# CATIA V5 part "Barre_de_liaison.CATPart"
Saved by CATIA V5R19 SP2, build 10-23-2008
Part number: Barre_de_liaison
Bounding box of the stored display mesh (mm): x -16 to -4, y -304 to 0, z -105.955 to -86.045
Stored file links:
  G:\EU_thinkMotion\CFAO_2010\MMS_groupe3\MMS_groupe3\pmayet\pmayet_assemblage_animation\pmayet_assemblage_animation\Barre_de_liaison.CATPart
  G:\EU_thinkMotion\CFAO_2010\MMS_groupe3\MMS_groupe3\pmayet\pmayet_assemblage_animation\pmayet_assemblage_animation\pmayet_assemblage_animation.CATProduct
  G:\EU_thinkMotion\CFAO_2010\MMS_groupe3\MMS_groupe3\pmayet\pmayet_assemblage_animation\pmayet_assemblage_animation\Squelette_barre_de_liaison.CATPart
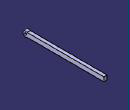
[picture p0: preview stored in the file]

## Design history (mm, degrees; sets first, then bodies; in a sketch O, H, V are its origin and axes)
Parameters
  Rayon_trou_barre_de_liaison = 4 mm
  Epaisseur_barre_de_liaison = 6 mm
Set1
  Plane1: linked copy from another document
  Point1 "Point.22_barre_liaison": linked copy from another document
  Line1: linked copy from another document
  Point2 "Point.23_barre_liaison_2": linked copy from another document
Body1 (main body)
  Sketch1 on Plane1, origin (-10, 0, 0), H (0, 1, 0), V (0, 0, 1)
    arc A1 centre (-294, -96) radius 10 from (-288, -88) to (-288, -104) ccw
    point P1 (-294, -96)
    point P2 (-288, -88)
    point P3 (-288, -104)
    line L1 (-288, -88) -> (0, -88)
    point P4 (-288, -88)
    point P5 (0, -88)
    line L2 (-288, -104) -> (0, -104)
    point P6 (-288, -104)
    point P7 (0, -104)
    line L3 (0, -88) -> (0, -104)
    point P8 (0, -88)
    point P9 (0, -104)
    circle A2 centre (-294, -96) radius 4
    point P10 (-294, -96)
    reference projected point E1 (-294, -96) from Point1
    reference projected point E2 (-294, -96) from Point1
    reference projected line E3 (-294, -96) -> (0, -96) from Line1
    reference projected line E4 (-294, -96) -> (0, -96) from Line1
    reference projected point E5 (0, -96) from Point2
    radius A1 = 10 {= Rayon_trou_barre_de_liaison *2.5}
    distance P10 A2 = 4 {= Rayon_trou_barre_de_liaison}
    distance E3 L1 = 8 {= Rayon_trou_barre_de_liaison *2}
    distance E4 L2 = 8 {= Rayon_trou_barre_de_liaison *2}
    length L3 = 16 {= Rayon_trou_barre_de_liaison *4}
    distance P7 P9 = 0
    horizontal: L1 H, L2 H
    vertical: L3 V
    coincidence: P1 E1, P10 E2, E5 L3, P5 P8, P3 P6, P2 P4
  Pad1: profile Sketch1, direction (1, 0, 0), length 6 {= Epaisseur_barre_de_liaison}, mirrored extent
